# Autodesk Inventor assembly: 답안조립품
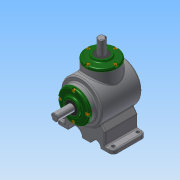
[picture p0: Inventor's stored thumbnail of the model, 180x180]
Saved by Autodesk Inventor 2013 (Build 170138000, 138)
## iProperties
Created: 2018-08
Part Number: 답안조립품
Document SubType Name: Assembly
Designer: Administrator
Author: Administrator
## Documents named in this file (14)
- C:\Users\Administrator\Desktop\480808V1018\답안조립품.iam
- C:\Users\Administrator\Desktop\480808V1018\본체.ipt
- C:\Users\Administrator\Desktop\480808V1018\메인 축.ipt
- 메인 축.ipt
- C:\Users\Administrator\Desktop\480808V1018\키 5x5.ipt
- C:\Users\Administrator\Desktop\480808V1018\키 4x4.ipt
- C:\Users\Administrator\Desktop\480808V1018\서브 축.ipt
- 서브 축.ipt
- C:\Users\Administrator\Desktop\480808V1018\서브 베벨기어.ipt
- C:\Users\Administrator\Desktop\480808V1018\메인 베벨기어.ipt
- C:\Users\Administrator\Desktop\480808V1018\베어링 6203.ipt
- C:\Users\Administrator\Desktop\480808V1018\커버.ipt
- C:\Users\Administrator\Desktop\480808V1018\오일실 17 32 8.ipt
- C:\Users\Administrator\Desktop\480808V1018\볼트 M4.ipt
